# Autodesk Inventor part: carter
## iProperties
Shininess: 64.0
Length Units: 11269
Angle Units: 11279
Time Units: 11290
Mass Units: 11283
Length Display Precision: 3
Angle Display Precision: 2
Compacted: True
Part Number: carter
Document SubType Name: Modeling
Created: 2003-05
Material: Delrin - Noir
Designer: Philippe
Density: 0.0
Volumn: 0.0
Area: 0.0
PropertySet Name: Model Information
Control State: 0
Master: False
Checked Out: False
Author: Philippe
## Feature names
1. Semelle [Extrusion]
2. Guidage axe [Revolution]
3. Cone à roulements [Revolution]
4. Rajout de matière [Extrusion]
5. Fente 1 [Extrusion]
6. Fente 2 [Extrusion]
7. Fente 3 [Extrusion]
8. Fente 4 [Extrusion]
9. Passage des fils [Extrusion]
10. Demi bossage [Extrusion]
11. Congé entre cylindres [Fillet]
12. Congé interne fente 1 [Fillet]
13. Congé externe fente 1 [Fillet]
14. Coque1
15. Portée de roulement [Extrusion]
16. Passage axe [Hole]
17. Bossages fixation moteur [Extrusion]
18. Perçage fixation moteur [Hole]
19. Ouvertures fentes [Extrusion]
20. 4 Congés angles vifs [Fillet]
21. Bosssages intérieur fentes [Extrusion]
22. Coin bas [Extrusion]
23. Coin haut gauche [Extrusion]
24. Coin haut droit [Extrusion]
25. Portée roulements vis [Revolution]
26. Symétrie protection roue [Mirror]
27. 2 bossages bas [Extrusion]
28. Congés coin bas [Fillet]
29. 6 bossages [Extrusion]
30. 2 bossages haut [Extrusion]
31. Bossage haut milieu [Extrusion]
32. Evidements bas moteur [Extrusion]
33. 2 Bossages bas moteur [Extrusion]
34. Congé cylidre vis [Fillet]
35. Symétrie nervures [Mirror]
36. Congé nervure [Fillet]
37. Perçages diam 5 [Hole]
38. Fin cylindre vis [Extrusion]
39. Appui moteur [Revolution]
40. Congés coins hauts ext [Fillet]
41. Congés coins hauts int [Fillet]
42. Révolution5 [Revolution]
43. Fond d'axe [Extrusion]
44. Passage accouplement [Revolution]
45. Passage vis moteur [Extrusion]
46. Symétrie vis moteur [Mirror]
47. Retrait Fond moteur [Extrusion]
48. Appui arrière moteur [Extrusion]
49. Passage arrière moteur [Extrusion]
50. Arrondi coin haut gauche [Extrusion]
51. Congé extérieur 12 [Fillet]
52. Congé extérieur 13 [Fillet]
53. Congé extérieur 14 [Fillet]
54. Congé extérieur 15 [Fillet]
55. Congé extérieur 16 [Fillet]
56. Congé extérieur 17 [Fillet]
57. Bouchage trou [Extrusion]
58. Bossage milieu haut [Extrusion]
59. Cavité supérieure [Extrusion]
60. 2e cavité supérieure [Rectangular Pattern]
61. Guidage de la roue [Extrusion]
62. Révolution7 [Revolution]
63. Extrusion33
